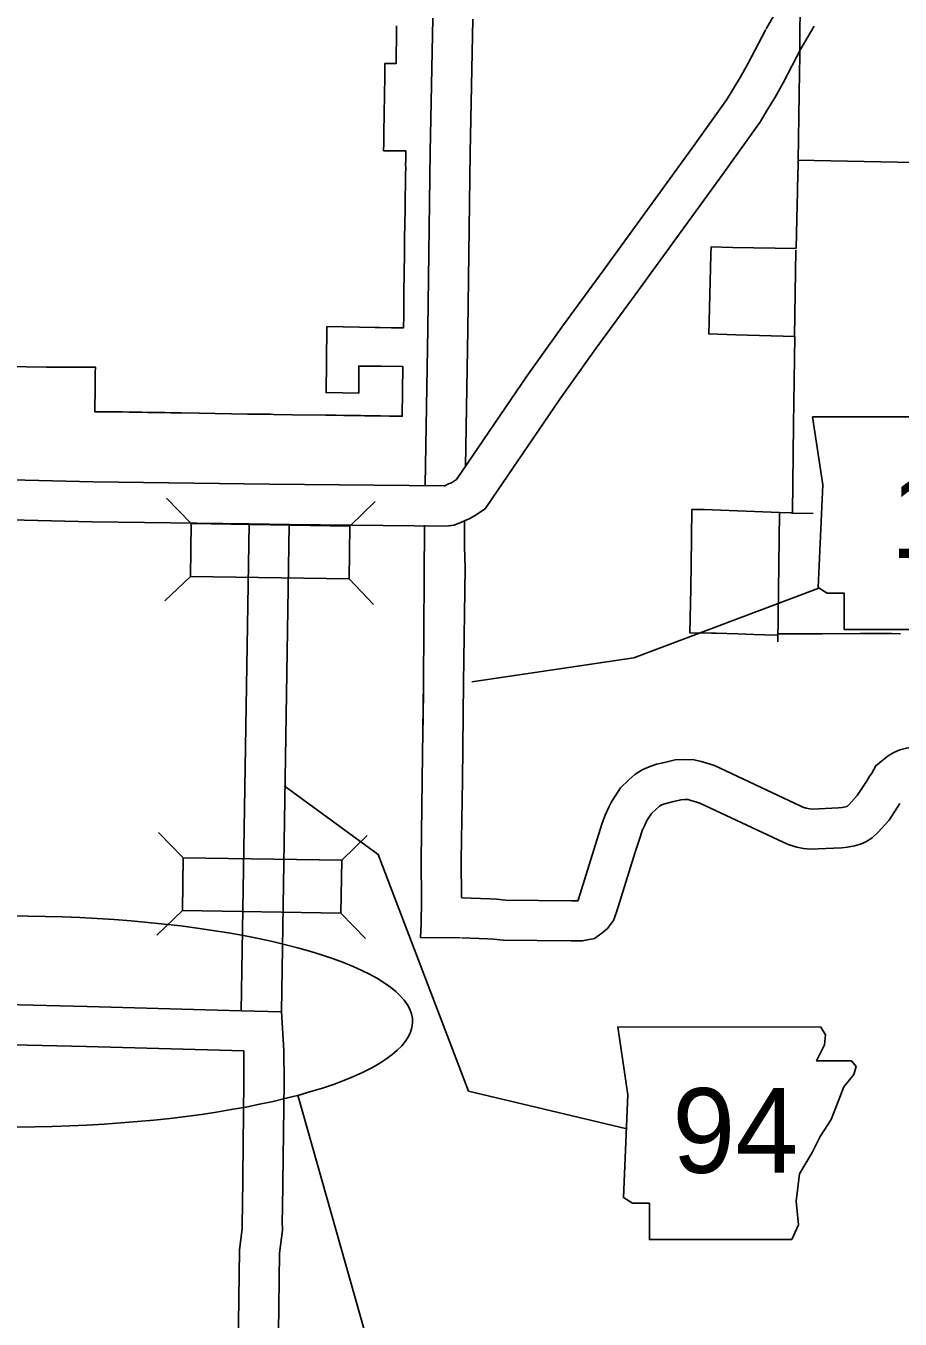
# Model space of a CAD drawing. Extents: x 309389.3 to 309420.2, y 336441.4 to 336461.2.
# Drawn here: x 309392.47 to 309393.462, y 336456.886 to 336458.352 of the extents above; entities that cross this region are included whole.
import ezdxf

# ---------------------------------------------------------------- set-up
doc = ezdxf.new("R2010")
doc.units = 0
for name, color, linetype in [('Level 24', 7, 'Continuous'), ('Level 37', 7, 'Continuous'), ('Level 4', 7, 'Continuous'), ('Level 48', 7, 'Continuous'), ('Level 62', 7, 'Continuous'), ('Level 63', 7, 'Continuous'), ('R_Axis Annot', 7, 'Continuous'), ('R_Contours', 7, 'Continuous'), ('R_Detour Annot', 7, 'Continuous'), ('R_Exist Surface Annot', 7, 'Continuous')]:
    doc.layers.add(name, color=color, linetype=linetype)

msp = doc.modelspace()

# ---------------------------------------------------------------- linework, layer by layer
at = {"layer": 'Level 24'}
for points in [[(309392.9316, 336458.3606), (309392.9286, 336458.2087), (309392.9262, 336458.0086), (309392.9229, 336457.8315)], [(309392.977, 336458.3597), (309392.9741, 336458.208), (309392.9716, 336458.0079), (309392.9688, 336457.8526)], [(309392.7467, 336457.8326), (309392.5464, 336457.8352), (309392.3457, 336457.8401), (309392.1411, 336457.8446), (309391.7472, 336457.8507), (309391.5941, 336457.8538)], [(309392.7234, 336457.7875), (309392.5456, 336457.7898), (309392.3447, 336457.7946), (309392.1403, 336457.7991), (309391.7464, 336457.8052), (309391.5876, 336457.8085)], [(309392.7233, 336457.7875), (309392.7145, 336457.2352)], [(309392.7687, 336457.7864), (309392.76, 336457.2345)], [(309392.9678, 336457.7911), (309392.9676, 336457.7613)], [(309393.668, 336457.5155), (309393.6575, 336457.5172), (309393.654, 336457.5176), (309393.6512, 336457.5183), (309393.6344, 336457.5237), (309393.6154, 336457.5282), (309393.602, 336457.5305), (309393.5955, 336457.5313), (309393.5858, 336457.5323), (309393.5728, 336457.532), (309393.4796, 336457.5351), (309393.4688, 336457.5333), (309393.4613, 336457.5312), (309393.4544, 336457.5283), (309393.4482, 336457.5245), (309393.4423, 336457.5201), (309393.4342, 336457.5133), (309393.4294, 336457.505), (309393.4267, 336457.5006), (309393.423, 336457.4946)], [(309393.4235, 336457.4953), (309393.4131, 336457.4794), (309393.4036, 336457.469), (309393.402, 336457.4675), (309393.4017, 336457.4673), (309393.4013, 336457.4671), (309393.3998, 336457.4667), (309393.3958, 336457.4661), (309393.3916, 336457.4656), (309393.3618, 336457.4641), (309393.3591, 336457.4645), (309393.3552, 336457.4652), (309393.3514, 336457.4664), (309393.3476, 336457.468), (309393.3427, 336457.4703), (309393.2511, 336457.5134), (309393.2426, 336457.5162), (309393.2359, 336457.5179), (309393.228, 336457.52), (309393.2174, 336457.5204), (309393.2067, 336457.5199), (309393.1945, 336457.517), (309393.1853, 336457.5149), (309393.1771, 336457.5122), (309393.1691, 336457.5087), (309393.161, 336457.5035), (309393.1539, 336457.4971), (309393.1447, 336457.4884), (309393.1385, 336457.4789), (309393.1344, 336457.4724), (309393.1314, 336457.4663), (309393.1271, 336457.4571), (309393.1239, 336457.448), (309393.1179, 336457.429), (309393.097, 336457.3621), (309393.0963, 336457.3601), (309393.089, 336457.3602), (309393.0143, 336457.3609), (309393.004, 336457.362), (309392.9962, 336457.3623), (309392.9646, 336457.3637)], [(309393.4615, 336457.4703), (309393.4491, 336457.4515), (309393.4363, 336457.4374), (309393.4301, 336457.4314), (309393.4228, 336457.4269), (309393.4169, 336457.4243), (309393.4099, 336457.4223), (309393.4021, 336457.421), (309393.3954, 336457.4202), (309393.3598, 336457.4185), (309393.352, 336457.4196), (309393.3444, 336457.4209), (309393.3358, 336457.4236), (309393.3289, 336457.4265), (309393.3232, 336457.4293), (309393.2345, 336457.471), (309393.23, 336457.4725), (309393.2242, 336457.474), (309393.2212, 336457.4748), (309393.2176, 336457.4749), (309393.2132, 336457.4747), (309393.2048, 336457.4727), (309393.1974, 336457.471), (309393.1932, 336457.4697), (309393.1907, 336457.4686), (309393.1888, 336457.4673), (309393.1848, 336457.4637), (309393.1798, 336457.459), (309393.1767, 336457.4544), (309393.1742, 336457.4503), (309393.1724, 336457.4466), (309393.1693, 336457.44), (309393.1671, 336457.4336), (309393.1612, 336457.4153), (309393.14, 336457.3473), (309393.1365, 336457.338), (309393.13, 336457.3288), (309393.1233, 336457.3233), (309393.1152, 336457.3175), (309393.1011, 336457.3146), (309393.0886, 336457.3148), (309393.0116, 336457.3155), (309393.0007, 336457.3166), (309392.9943, 336457.3169), (309392.9643, 336457.3183)]]:
    msp.add_lwpolyline(points, dxfattribs=at)
at = {"layer": 'Level 37'}
for p, q in [((309392.6577, 336457.7878), (309392.6299, 336457.8166)), ((309392.8377, 336457.785), (309392.8664, 336457.8128)), ((309392.6568, 336457.7278), (309392.628, 336457.7)), ((309392.8368, 336457.725), (309392.8646, 336457.6962)), ((309392.6486, 336457.409), (309392.6208, 336457.4377)), ((309392.8286, 336457.4062), (309392.8573, 336457.434)), ((309392.6486, 336457.409), (309392.6477, 336457.349)), ((309392.8286, 336457.4062), (309392.6486, 336457.409)), ((309392.8276, 336457.3462), (309392.8286, 336457.4062)), ((309392.6477, 336457.349), (309392.6189, 336457.3212)), ((309392.6477, 336457.349), (309392.8276, 336457.3462)), ((309392.8276, 336457.3462), (309392.8555, 336457.3174))]:
    msp.add_line(p, q, dxfattribs=at)
msp.add_lwpolyline([(309392.8377, 336457.785), (309392.6577, 336457.7878), (309392.6568, 336457.7278), (309392.8368, 336457.725)], close=True, dxfattribs=at)
at = {"layer": 'Level 4'}
for points in [[(309394.0952, 336458.184), (309393.7421, 336458.1919), (309393.3454, 336458.1996)], [(309393.3435, 336458.0978), (309393.3419, 336458)], [(309393.3247, 336457.7995), (309393.3231, 336457.6536)]]:
    msp.add_lwpolyline(points, dxfattribs=at)
at = {"layer": 'Level 48'}
msp.add_lwpolyline([(309393.3632, 336457.7992), (309393.3386, 336457.7996)], dxfattribs=at)
at = {"layer": 'Level 62'}
for points in [[(309392.8906, 336458.352), (309392.8905, 336458.3466), (309392.8905, 336458.3414), (309392.8904, 336458.3361), (309392.8904, 336458.3307), (309392.8903, 336458.3254), (309392.8903, 336458.3201), (309392.8902, 336458.3148), (309392.89, 336458.3091), (309392.8809, 336458.3094), (309392.8774, 336458.3094), (309392.8774, 336458.2973), (309392.8773, 336458.292), (309392.8772, 336458.2867), (309392.8771, 336458.2814), (309392.877, 336458.2761), (309392.8769, 336458.2708), (309392.8768, 336458.2655), (309392.8767, 336458.2602), (309392.8766, 336458.2549), (309392.8765, 336458.2496), (309392.8764, 336458.2443), (309392.8763, 336458.239), (309392.8762, 336458.2337), (309392.8762, 336458.2284), (309392.8761, 336458.2231), (309392.876, 336458.2178), (309392.8759, 336458.2115), (309392.8758, 336458.2104), (309392.8759, 336458.2103), (309392.8871, 336458.2101), (309392.9011, 336458.2101), (309392.9011, 336458.1988), (309392.9009, 336458.1949), (309392.901, 336458.1912), (309392.9009, 336458.1836), (309392.9007, 336458.1765), (309392.9006, 336458.1688), (309392.9005, 336458.1613), (309392.9004, 336458.1547), (309392.9003, 336458.1506), (309392.9003, 336458.1497), (309392.9003, 336458.1445), (309392.9002, 336458.1385), (309392.9001, 336458.1327), (309392.9, 336458.1271), (309392.8999, 336458.1222), (309392.8998, 336458.1166), (309392.8997, 336458.1098), (309392.8997, 336458.1079), (309392.8997, 336458.1068), (309392.8995, 336458.0917), (309392.8993, 336458.074), (309392.899, 336458.0469), (309392.8987, 336458.0214), (309392.8985, 336458.0115), (309392.8984, 336458.0096), (309392.885, 336458.0098), (309392.8716, 336458.01), (309392.8665, 336458.0101)], [(309392.8906, 336458.352), (309392.8905, 336458.3466), (309392.8905, 336458.3414), (309392.8904, 336458.3361), (309392.8904, 336458.3307), (309392.8903, 336458.3254), (309392.8903, 336458.3201), (309392.8902, 336458.3148), (309392.89, 336458.3091), (309392.8809, 336458.3094), (309392.8774, 336458.3094), (309392.8774, 336458.2973), (309392.8773, 336458.292), (309392.8772, 336458.2867), (309392.8771, 336458.2814), (309392.877, 336458.2761), (309392.8769, 336458.2708), (309392.8768, 336458.2655), (309392.8767, 336458.2602), (309392.8766, 336458.2549), (309392.8765, 336458.2496), (309392.8764, 336458.2443), (309392.8763, 336458.239), (309392.8762, 336458.2337), (309392.8762, 336458.2284), (309392.8761, 336458.2231), (309392.876, 336458.2178), (309392.8759, 336458.2115), (309392.8758, 336458.2104), (309392.8759, 336458.2103), (309392.8871, 336458.2101), (309392.9011, 336458.2101), (309392.9011, 336458.1988)], [(309393.2957, 336457.6621), (309393.2777, 336457.6627), (309393.253, 336457.6634), (309393.2479, 336457.6636), (309393.2231, 336457.6641), (309393.2242, 336457.7142), (309393.2242, 336457.7158), (309393.2247, 336457.7405), (309393.2253, 336457.8037), (309393.2394, 336457.8036), (309393.3247, 336457.8002), (309393.3395, 336457.7999), (309393.3407, 336457.9), (309393.3421, 336457.9999), (309393.2754, 336458.0018), (309393.2447, 336458.0027), (309393.2451, 336458.0172), (309393.247, 336458.0924), (309393.2473, 336458.1013), (309393.272, 336458.1009), (309393.3437, 336458.0996), (309393.3449, 336458.1497), (309393.345, 336458.1523), (309393.3452, 336458.1602), (309393.3454, 336458.1681), (309393.3461, 336458.1954), (309393.3461, 336458.1977), (309393.3462, 336458.2), (309393.3465, 336458.2237), (309393.3469, 336458.2498), (309393.3473, 336458.2746), (309393.3476, 336458.2997), (309393.3478, 336458.3165), (309393.3478, 336458.3205), (309393.3479, 336458.325), (309393.348, 336458.3411), (309393.3481, 336458.3498), (309393.3482, 336458.3636)], [(309392.9011, 336458.1988), (309392.9009, 336458.1949), (309392.901, 336458.1912), (309392.9009, 336458.1836), (309392.9007, 336458.1765), (309392.9006, 336458.1688), (309392.9005, 336458.1613), (309392.9004, 336458.1547), (309392.9003, 336458.1506), (309392.9003, 336458.1497), (309392.9003, 336458.1445), (309392.9002, 336458.1385), (309392.9001, 336458.1327), (309392.9, 336458.1271), (309392.8999, 336458.1222), (309392.8998, 336458.1166), (309392.8997, 336458.1098), (309392.8997, 336458.1079), (309392.8997, 336458.1068), (309392.8995, 336458.0917), (309392.8993, 336458.074), (309392.899, 336458.0469), (309392.8987, 336458.0214), (309392.8985, 336458.0115), (309392.8984, 336458.0096), (309392.885, 336458.0098), (309392.8716, 336458.01), (309392.8665, 336458.0101), (309392.8487, 336458.0104), (309392.8116, 336458.011), (309392.8112, 336457.9706), (309392.8106, 336457.9362), (309392.8478, 336457.9357), (309392.8478, 336457.9663), (309392.8734, 336457.9662), (309392.8978, 336457.9658), (309392.8971, 336457.9094), (309392.8949, 336457.9095), (309392.8897, 336457.9095), (309392.8825, 336457.9096), (309392.8723, 336457.9098), (309392.872, 336457.9098), (309392.8547, 336457.91), (309392.8502, 336457.9101), (309392.8474, 336457.9101), (309392.8463, 336457.9101), (309392.8426, 336457.9102), (309392.8388, 336457.9103), (309392.8346, 336457.9103), (309392.8307, 336457.9104), (309392.8222, 336457.9105), (309392.8105, 336457.9107), (309392.7725, 336457.9112), (309392.751, 336457.9115), (309392.7478, 336457.9116), (309392.7377, 336457.9116), (309392.7241, 336457.9119), (309392.7216, 336457.9119), (309392.6667, 336457.9128), (309392.6468, 336457.9132), (309392.6406, 336457.9133), (309392.6342, 336457.9134), (309392.6277, 336457.9135), (309392.6213, 336457.9136), (309392.6148, 336457.9137), (309392.6084, 336457.9138), (309392.6017, 336457.914), (309392.5984, 336457.9139), (309392.5945, 336457.914), (309392.5873, 336457.9141), (309392.5798, 336457.9143), (309392.5718, 336457.9144), (309392.5485, 336457.9146), (309392.5489, 336457.9427), (309392.5489, 336457.9591), (309392.5491, 336457.9652), (309392.5131, 336457.9649), (309392.4937, 336457.9651), (309392.4482, 336457.9657)], [(309392.8665, 336458.0101), (309392.8487, 336458.0104), (309392.8116, 336458.011), (309392.8112, 336457.9706), (309392.8106, 336457.9362), (309392.8478, 336457.9357), (309392.8478, 336457.9663), (309392.8734, 336457.9662), (309392.8978, 336457.9658), (309392.8971, 336457.9094), (309392.8949, 336457.9095), (309392.8897, 336457.9095), (309392.8825, 336457.9096), (309392.8723, 336457.9098), (309392.872, 336457.9098), (309392.8547, 336457.91), (309392.8502, 336457.9101), (309392.8474, 336457.9101), (309392.8463, 336457.9101), (309392.8426, 336457.9102), (309392.8388, 336457.9103), (309392.8346, 336457.9103), (309392.8307, 336457.9104), (309392.8222, 336457.9105), (309392.8105, 336457.9107), (309392.7725, 336457.9112), (309392.751, 336457.9115), (309392.7478, 336457.9116), (309392.7377, 336457.9116), (309392.7241, 336457.9119), (309392.7216, 336457.9119), (309392.6667, 336457.9128), (309392.6468, 336457.9132), (309392.6406, 336457.9133), (309392.6342, 336457.9134), (309392.6277, 336457.9135), (309392.6213, 336457.9136), (309392.6148, 336457.9137), (309392.6084, 336457.9138), (309392.6017, 336457.914), (309392.5984, 336457.9139), (309392.5945, 336457.914), (309392.5873, 336457.9141), (309392.5798, 336457.9143), (309392.5718, 336457.9144), (309392.5485, 336457.9146), (309392.5489, 336457.9427), (309392.5489, 336457.9591), (309392.5491, 336457.9652), (309392.5131, 336457.9649), (309392.4937, 336457.9651), (309392.4482, 336457.9657)], [(309393.4622, 336457.6629), (309393.4522, 336457.663), (309393.4453, 336457.663), (309393.4434, 336457.663), (309393.4232, 336457.663), (309393.4163, 336457.663), (309393.3734, 336457.6628), (309393.3231, 336457.6629), (309393.3231, 336457.6612), (309393.3078, 336457.6617), (309393.2957, 336457.6621)]]:
    msp.add_lwpolyline(points, dxfattribs=at)
at = {"layer": 'Level 63'}
msp.add_line((309393.4111, 336454.9055), (309392.7786, 336457.1397), dxfattribs=at)
at = {"layer": 'R_Axis Annot'}
for points in [[(309393.3098, 336458.3486), (309393.3248, 336458.3745)], [(309393.3492, 336458.3258), (309393.3642, 336458.3517)], [(309392.9585, 336457.8376), (309393.0384, 336457.9548), (309393.0799, 336458.013), (309393.1245, 336458.0738), (309393.2256, 336458.213), (309393.2651, 336458.2684), (309393.2715, 336458.279), (309393.2803, 336458.2934), (309393.2888, 336458.309), (309393.3094, 336458.3478)], [(309392.9911, 336457.8045), (309392.999, 336457.8163), (309393.0757, 336457.9288), (309393.1167, 336457.9863), (309393.1612, 336458.047), (309393.2625, 336458.1864), (309393.3032, 336458.2435), (309393.3103, 336458.2554), (309393.3197, 336458.2705), (309393.3289, 336458.2875), (309393.3496, 336458.3265)], [(309392.7466, 336457.8326), (309392.9445, 336457.8305), (309392.9453, 336457.8306), (309392.9455, 336457.8307), (309392.9497, 336457.8328), (309392.9529, 336457.8341), (309392.9552, 336457.8354), (309392.9585, 336457.8376)], [(309392.7687, 336457.7869), (309392.9463, 336457.785), (309392.9561, 336457.7859), (309392.9643, 336457.7892), (309392.9686, 336457.7914), (309392.973, 336457.7932), (309392.979, 336457.7967), (309392.9911, 336457.8045)], [(309392.7687, 336457.7869), (309392.7234, 336457.7875)], [(309392.9223, 336457.7859), (309392.921, 336457.6083)], [(309392.9685, 336457.7376), (309392.9676, 336457.7613)], [(309392.9642, 336457.3637), (309392.964, 336457.4062), (309392.9653, 336457.4968), (309392.9667, 336457.6076), (309392.9685, 336457.7376)], [(309392.9177, 336457.3186), (309392.9185, 336457.3341), (309392.9188, 336457.361), (309392.9185, 336457.4063), (309392.9198, 336457.4974), (309392.9213, 336457.6084)], [(309392.9213, 336457.6084), (309392.9206, 336457.5593)], [(309392.9632, 336457.3183), (309392.9177, 336457.3186)], [(309392.7145, 336457.2356), (309392.5398, 336457.2405), (309392.3399, 336457.2452), (309392.1422, 336457.2485), (309391.9172, 336457.2524), (309391.7378, 336457.2566), (309391.4857, 336457.2628)], [(309392.7145, 336457.2356), (309392.76, 336457.2343)], [(309392.76, 336457.2345), (309392.7629, 336457.1904)], [(309392.7175, 336457.19), (309392.5386, 336457.195), (309392.339, 336457.1997), (309392.1414, 336457.203), (309391.9163, 336457.207), (309391.7367, 336457.2112), (309391.478, 336457.2175)], [(309392.7077, 336456.5873), (309392.7081, 336456.6325), (309392.7125, 336456.9642), (309392.7157, 336456.9888), (309392.7154, 336456.9973), (309392.7159, 336457.0121), (309392.7176, 336457.1549), (309392.7174, 336457.19)], [(309392.7536, 336456.6308), (309392.7579, 336456.9609), (309392.7613, 336456.9867), (309392.7609, 336456.9973), (309392.7614, 336457.011), (309392.763, 336457.1548), (309392.7629, 336457.1904)]]:
    msp.add_lwpolyline(points, dxfattribs=at)
at = {"layer": 'R_Contours'}
for points in [[(309393.3624, 336457.9087), (309393.3739, 336457.8318), (309393.3688, 336457.7152), (309393.379, 336457.7088), (309393.3983, 336457.7088), (309393.3983, 336457.6678), (309393.5598, 336457.6678), (309393.5675, 336457.6844), (309393.5649, 336457.7114), (309393.5687, 336457.7421), (309393.5828, 336457.7665), (309393.5918, 336457.7844), (309393.6046, 336457.8036), (309393.6123, 336457.8241), (309393.6187, 336457.8408), (309393.6303, 336457.8549), (309393.6328, 336457.8639), (309393.6277, 336457.8703), (309393.588, 336457.8703), (309393.5969, 336457.8882), (309393.5982, 336457.8998), (309393.5929, 336457.9086)], [(309393.1414, 336457.2172), (309393.1529, 336457.1403), (309393.1478, 336457.0237), (309393.1581, 336457.0173), (309393.1773, 336457.0173), (309393.1773, 336456.9762), (309393.3388, 336456.9762), (309393.3465, 336456.9929), (309393.3439, 336457.0198), (309393.3477, 336457.0506), (309393.3618, 336457.0749), (309393.3708, 336457.0929), (309393.3836, 336457.1121), (309393.3913, 336457.1326), (309393.3977, 336457.1493), (309393.4093, 336457.1634), (309393.4118, 336457.1723), (309393.4067, 336457.1787), (309393.367, 336457.1787), (309393.3759, 336457.1967), (309393.3772, 336457.2082), (309393.3719, 336457.2171)]]:
    msp.add_lwpolyline(points, close=True, dxfattribs=at)
msp.add_lwpolyline([(309392.7632, 336457.4906), (309392.8696, 336457.4127), (309392.9723, 336457.1444), (309393.1516, 336457.1017)], dxfattribs=at)
at = {"layer": 'R_Detour Annot'}
for p, q in [((309393.3695, 336457.7147), (309393.1597, 336457.6357)), ((309393.1597, 336457.6357), (309392.9759, 336457.6085))]:
    msp.add_line(p, q, dxfattribs=at)
at = {"layer": 'R_Exist Surface Annot'}
msp.add_ellipse((309392.4506, 336457.2233), major_axis=(0.4581, 0), ratio=0.261367, start_param=4.420709, end_param=10.044947, dxfattribs=at)

# ---------------------------------------------------------------- texts
at = {"layer": 'R_Contours'}
for s, p in [('12', (309393.4507, 336457.7489)), ('94', (309393.2033, 336457.0518))]:
    msp.add_text(s, height=0.096, dxfattribs=at).set_placement(p)

doc.saveas('drawing.dxf')
